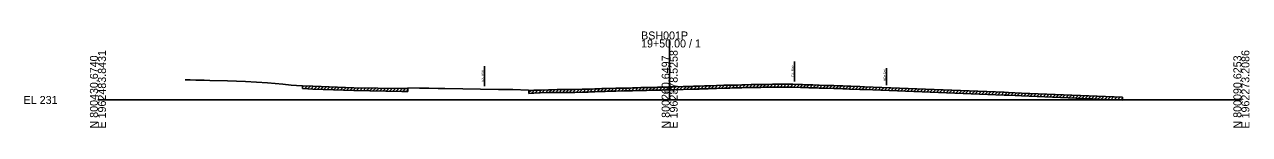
# Model space of a CAD drawing. Extents: x -26 to 1403, y -10 to 19587.
# Drawn here: x -25.7 to 402.8, y 3490.3 to 3524 of the extents above; entities that cross this region are included whole.
import ezdxf

# ---------------------------------------------------------------- set-up
doc = ezdxf.new("R2010")
doc.units = 0
for name, color, linetype in [('Default', 7, 'Continuous'), ('RD_GPK_XS_Cell', 7, 'Continuous'), ('RD_XS_ExGround', 7, 'Continuous'), ('RD_XS_ExPaveRet', 7, 'Continuous'), ('RD_XS_ExRW', 7, 'Continuous'), ('RD_XS_NewRW', 7, 'Continuous'), ('RD_XS_TX_Elev_EX', 7, 'Continuous')]:
    doc.layers.add(name, color=color, linetype=linetype)

msp = doc.modelspace()

# ---------------------------------------------------------------- linework, layer by layer
at = {"layer": 'RD_GPK_XS_Cell'}
for p, q in [((200, 3500), (200, 3521.2)), ((0, 3500), (200, 3500)), ((200, 3500), (400, 3500))]:
    msp.add_line(p, q, dxfattribs=at)
at = {"layer": 'RD_XS_ExGround'}
msp.add_lwpolyline([(30.51, 3507.07), (31.26, 3507.05), (32.27, 3507.02), (34.23, 3506.99), (34.54, 3506.98), (35.46, 3506.97), (37.12, 3506.93), (39.18, 3506.87), (45.29, 3506.73), (51.6, 3506.44), (59.31, 3505.96), (64.64, 3505.48), (67.56, 3505.22), (69.44, 3505.1), (71.57, 3504.97), (75.23, 3504.8), (89.48, 3504.28), (106.25, 3504.01), (108.35, 3503.97), (108.45, 3504.22), (112.53, 3504.15), (115.74, 3504.1), (118.96, 3504.04), (121.32, 3504.02), (140.09, 3503.71), (143.93, 3503.66), (145.18, 3503.61), (150.67, 3503.43), (150.77, 3503.18), (150.79, 3503.32), (151.75, 3503.36), (152.52, 3503.38), (154.65, 3503.45), (157.62, 3503.56), (158.14, 3503.57), (160.67, 3503.62), (161.67, 3503.62), (162.1, 3503.62), (163.47, 3503.62), (165.46, 3503.64), (166.37, 3503.65), (166.78, 3503.66), (169.36, 3503.73), (170.2, 3503.75), (171.49, 3503.79), (172.3, 3503.82), (173.84, 3503.88), (175.23, 3503.93), (175.62, 3503.94), (176.27, 3503.97), (177.47, 3504.02), (178.18, 3504.04), (181.18, 3504.09), (184.02, 3504.15), (184.7, 3504.17), (185.73, 3504.19), (186.95, 3504.22), (188.32, 3504.26), (189.91, 3504.32), (190.5, 3504.33), (191.94, 3504.37), (192.85, 3504.38), (195.24, 3504.42), (195.79, 3504.44), (197.4, 3504.47), (198.73, 3504.51), (199.2, 3504.52), (200, 3504.55), (201.04, 3504.58), (201.69, 3504.6), (204.75, 3504.69), (207.58, 3504.77), (208.32, 3504.79), (209.52, 3504.82), (210.15, 3504.84), (210.53, 3504.86), (212.16, 3504.91), (213.47, 3504.95), (214.26, 3504.98), (216.4, 3505.06), (219, 3505.13), (219.32, 3505.13), (221.02, 3505.17), (222.25, 3505.2), (223.73, 3505.24), (225.2, 3505.28), (226.45, 3505.33), (228.54, 3505.4), (229.84, 3505.39), (231.08, 3505.4), (231.89, 3505.42), (233.21, 3505.45), (233.71, 3505.46), (234.01, 3505.47), (236, 3505.51), (236.36, 3505.52), (236.91, 3505.52), (238.03, 3505.51), (239.19, 3505.51), (239.91, 3505.5), (243.03, 3505.48), (245.76, 3505.39), (246.43, 3505.38), (247.46, 3505.35), (248.23, 3505.32), (248.73, 3505.31), (250.09, 3505.26), (251.67, 3505.21), (252.29, 3505.19), (254.56, 3505.12), (257.45, 3505.04), (259.15, 3504.98), (260.54, 3504.93), (261.99, 3504.87), (262.86, 3504.84), (263.37, 3504.82), (266.52, 3504.71), (268.11, 3504.66), (316.99, 3502.69), (318.58, 3502.63), (323.1, 3502.44), (358.39, 3500.93)], dxfattribs=at)
at = {"layer": 'RD_XS_ExPaveRet'}
for p, q in [((227.88, 3504.38), (228.9, 3505.4)), ((230.25, 3504.39), (231.26, 3505.41)), ((231.45, 3504.41), (232.47, 3505.43)), ((232.65, 3504.44), (233.67, 3505.46)), ((233.85, 3504.46), (234.88, 3505.49)), ((235.06, 3504.49), (236.08, 3505.51)), ((236.27, 3504.52), (237.27, 3505.52)), ((237.44, 3504.52), (238.44, 3505.51)), ((238.62, 3504.51), (239.61, 3505.51)), ((239.79, 3504.5), (240.78, 3505.49)), ((240.95, 3504.49), (241.95, 3505.48)), ((242.12, 3504.48), (243.11, 3505.47)), ((243.28, 3504.47), (244.26, 3505.44)), ((244.43, 3504.43), (245.4, 3505.4)), ((71.57, 3503.97), (71.57, 3504.97)), ((71.57, 3504.45), (72.06, 3504.95)), ((72.23, 3503.94), (73.19, 3504.89)), ((73.36, 3503.89), (74.31, 3504.84)), ((74.49, 3503.84), (75.44, 3504.79)), ((75.62, 3503.79), (76.58, 3504.75)), ((76.75, 3503.75), (77.72, 3504.71)), ((77.89, 3503.7), (78.85, 3504.67)), ((79.02, 3503.66), (79.99, 3504.63)), ((80.16, 3503.62), (81.13, 3504.59)), ((81.3, 3503.58), (82.26, 3504.54)), ((82.43, 3503.54), (83.4, 3504.5)), ((83.57, 3503.5), (84.54, 3504.46)), ((84.71, 3503.46), (85.67, 3504.42)), ((85.84, 3503.41), (86.81, 3504.38)), ((86.98, 3503.37), (87.94, 3504.34)), ((88.12, 3503.33), (89.08, 3504.3)), ((89.25, 3503.29), (90.23, 3504.27)), ((90.41, 3503.27), (91.39, 3504.25)), ((91.57, 3503.25), (92.55, 3504.23)), ((92.73, 3503.23), (93.71, 3504.21)), ((93.88, 3503.21), (94.87, 3504.19)), ((95.04, 3503.19), (96.03, 3504.17)), ((96.2, 3503.17), (97.19, 3504.15)), ((97.36, 3503.15), (98.35, 3504.14)), ((98.52, 3503.13), (99.5, 3504.12)), ((99.68, 3503.11), (100.66, 3504.1)), ((100.84, 3503.09), (101.82, 3504.08)), ((102, 3503.08), (102.98, 3504.06)), ((103.16, 3503.06), (104.14, 3504.04)), ((104.32, 3503.04), (105.3, 3504.02)), ((105.47, 3503.02), (106.46, 3504)), ((106.63, 3503), (107.62, 3503.98)), ((107.79, 3502.98), (108.35, 3503.53)), ((108.35, 3502.97), (108.35, 3503.97)), ((150.79, 3502.68), (151.45, 3503.34)), ((150.79, 3502.32), (150.79, 3503.32)), ((151.64, 3502.35), (152.67, 3503.39)), ((152.86, 3502.39), (153.89, 3503.43)), ((154.08, 3502.43), (155.11, 3503.47)), ((155.3, 3502.48), (156.33, 3503.51)), ((156.52, 3502.52), (157.56, 3503.56)), ((157.74, 3502.56), (158.76, 3503.58)), ((158.94, 3502.59), (159.96, 3503.61)), ((160.14, 3502.61), (161.15, 3503.62)), ((161.33, 3502.62), (162.33, 3503.62)), ((162.51, 3502.62), (163.51, 3503.62)), ((163.69, 3502.62), (164.7, 3503.63)), ((164.88, 3502.63), (165.89, 3503.65)), ((166.07, 3502.65), (167.09, 3503.67)), ((167.27, 3502.67), (168.3, 3503.7)), ((168.48, 3502.7), (169.51, 3503.73)), ((169.69, 3502.74), (170.72, 3503.77)), ((170.91, 3502.77), (171.94, 3503.81)), ((172.12, 3502.81), (173.16, 3503.85)), ((173.35, 3502.86), (174.39, 3503.9)), ((174.57, 3502.9), (175.61, 3503.94)), ((175.8, 3502.95), (176.84, 3503.99)), ((177.02, 3503), (178.06, 3504.04)), ((178.24, 3503.04), (179.26, 3504.06)), ((179.44, 3503.06), (180.46, 3504.08)), ((180.64, 3503.08), (181.66, 3504.1)), ((181.84, 3503.11), (182.87, 3504.13)), ((183.05, 3503.13), (184.07, 3504.15)), ((184.25, 3503.16), (185.27, 3504.18)), ((185.46, 3503.19), (186.48, 3504.21)), ((186.67, 3503.22), (187.69, 3504.25)), ((187.88, 3503.25), (188.91, 3504.28)), ((189.09, 3503.29), (190.13, 3504.32)), ((190.31, 3503.33), (191.34, 3504.35)), ((191.52, 3503.36), (192.53, 3504.37)), ((192.71, 3503.38), (193.73, 3504.39)), ((193.91, 3503.4), (194.93, 3504.42)), ((195.12, 3503.42), (196.14, 3504.44)), ((196.32, 3503.45), (197.34, 3504.47)), ((197.52, 3503.47), (198.55, 3504.5)), ((198.73, 3503.51), (199.77, 3504.54)), ((199.95, 3503.55), (200.99, 3504.58)), ((201.17, 3503.59), (202.2, 3504.62)), ((202.38, 3503.62), (203.42, 3504.65)), ((203.6, 3503.66), (204.63, 3504.69)), ((204.81, 3503.69), (205.84, 3504.72)), ((206.02, 3503.73), (207.05, 3504.75)), ((207.23, 3503.76), (208.26, 3504.79)), ((208.45, 3503.79), (209.48, 3504.82)), ((209.66, 3503.83), (210.69, 3504.86)), ((210.88, 3503.87), (211.91, 3504.9)), ((212.09, 3503.91), (213.13, 3504.94)), ((213.31, 3503.95), (214.35, 3504.98)), ((214.53, 3503.99), (215.57, 3505.03)), ((215.76, 3504.03), (216.79, 3505.07)), ((216.97, 3504.07), (218, 3505.1)), ((218.18, 3504.1), (219.21, 3505.13)), ((219.39, 3504.13), (220.41, 3505.15)), ((220.59, 3504.16), (221.61, 3505.18)), ((221.8, 3504.18), (222.82, 3505.21)), ((223.01, 3504.22), (224.04, 3505.25)), ((224.22, 3504.25), (225.25, 3505.29)), ((225.44, 3504.29), (226.47, 3505.33)), ((226.66, 3504.33), (227.7, 3505.37)), ((229.08, 3504.4), (230.07, 3505.39)), ((245.57, 3504.4), (246.55, 3505.37)), ((246.72, 3504.37), (247.69, 3505.34)), ((247.86, 3504.34), (248.83, 3505.3)), ((249, 3504.3), (249.97, 3505.27)), ((250.14, 3504.26), (251.11, 3505.23)), ((251.28, 3504.22), (252.25, 3505.19)), ((252.42, 3504.18), (253.4, 3505.16)), ((253.57, 3504.15), (254.54, 3505.12)), ((254.71, 3504.12), (255.68, 3505.09)), ((255.86, 3504.08), (256.83, 3505.06)), ((257, 3504.05), (257.97, 3505.02)), ((258.15, 3504.02), (259.12, 3504.99)), ((259.29, 3503.98), (260.25, 3504.94)), ((260.42, 3503.93), (261.38, 3504.9)), ((261.55, 3503.89), (262.52, 3504.86)), ((262.69, 3503.85), (263.65, 3504.81)), ((263.83, 3503.81), (264.79, 3504.77)), ((264.96, 3503.76), (265.93, 3504.73)), ((266.1, 3503.72), (267.07, 3504.69)), ((267.24, 3503.68), (268.21, 3504.65)), ((268.38, 3503.65), (269.34, 3504.61)), ((269.51, 3503.6), (270.47, 3504.56)), ((270.64, 3503.56), (271.61, 3504.52)), ((271.78, 3503.51), (272.74, 3504.47)), ((272.91, 3503.46), (273.87, 3504.43)), ((274.04, 3503.42), (275, 3504.38)), ((275.18, 3503.37), (276.14, 3504.34)), ((276.31, 3503.33), (277.27, 3504.29)), ((277.44, 3503.28), (278.4, 3504.24)), ((278.57, 3503.24), (279.53, 3504.2)), ((279.71, 3503.19), (280.67, 3504.15)), ((280.84, 3503.15), (281.8, 3504.11)), ((281.97, 3503.1), (282.93, 3504.06)), ((283.1, 3503.06), (284.06, 3504.02)), ((284.24, 3503.01), (285.2, 3503.97)), ((285.37, 3502.96), (286.33, 3503.93)), ((286.5, 3502.92), (287.46, 3503.88)), ((287.63, 3502.87), (288.59, 3503.83)), ((288.77, 3502.83), (289.73, 3503.79)), ((289.9, 3502.78), (290.86, 3503.74)), ((291.03, 3502.74), (291.99, 3503.7)), ((292.16, 3502.69), (293.12, 3503.65)), ((293.3, 3502.65), (294.26, 3503.61)), ((294.43, 3502.6), (295.39, 3503.56)), ((295.56, 3502.55), (296.52, 3503.52)), ((296.69, 3502.51), (297.65, 3503.47)), ((297.83, 3502.46), (298.79, 3503.43)), ((298.96, 3502.42), (299.92, 3503.38)), ((300.09, 3502.37), (301.05, 3503.33)), ((301.22, 3502.33), (302.19, 3503.29)), ((302.36, 3502.28), (303.32, 3503.24)), ((303.49, 3502.24), (304.45, 3503.2)), ((304.62, 3502.19), (305.58, 3503.15)), ((305.75, 3502.15), (306.72, 3503.11)), ((306.89, 3502.1), (307.85, 3503.06)), ((308.02, 3502.05), (308.98, 3503.02)), ((309.15, 3502.01), (310.11, 3502.97)), ((310.28, 3501.96), (311.25, 3502.92)), ((311.42, 3501.92), (312.38, 3502.88)), ((312.55, 3501.87), (313.51, 3502.83)), ((313.68, 3501.83), (314.64, 3502.79)), ((314.81, 3501.78), (315.78, 3502.74)), ((315.95, 3501.74), (316.91, 3502.7)), ((317.08, 3501.69), (318.04, 3502.65)), ((318.21, 3501.64), (319.17, 3502.6)), ((319.34, 3501.6), (320.3, 3502.56)), ((320.47, 3501.55), (321.44, 3502.51)), ((321.61, 3501.51), (322.57, 3502.47)), ((322.74, 3501.46), (323.7, 3502.42)), ((323.87, 3501.41), (324.83, 3502.37)), ((325, 3501.36), (325.96, 3502.32)), ((326.13, 3501.31), (327.09, 3502.27)), ((327.26, 3501.27), (328.22, 3502.22)), ((328.39, 3501.22), (329.34, 3502.18)), ((329.52, 3501.17), (330.47, 3502.13)), ((330.64, 3501.12), (331.6, 3502.08)), ((331.77, 3501.07), (332.73, 3502.03)), ((332.9, 3501.02), (333.86, 3501.98)), ((334.03, 3500.97), (334.99, 3501.93)), ((335.16, 3500.93), (336.12, 3501.88)), ((336.29, 3500.88), (337.25, 3501.84)), ((337.42, 3500.83), (338.38, 3501.79)), ((338.55, 3500.78), (339.51, 3501.74)), ((339.68, 3500.73), (340.64, 3501.69)), ((340.81, 3500.68), (341.77, 3501.64)), ((341.94, 3500.63), (342.9, 3501.59)), ((343.07, 3500.58), (344.03, 3501.54)), ((344.2, 3500.54), (345.16, 3501.49)), ((345.33, 3500.49), (346.29, 3501.45)), ((346.46, 3500.44), (347.42, 3501.4)), ((347.59, 3500.39), (348.54, 3501.35)), ((348.72, 3500.34), (349.67, 3501.3)), ((349.84, 3500.29), (350.8, 3501.25)), ((350.97, 3500.24), (351.93, 3501.2)), ((352.1, 3500.2), (353.06, 3501.15)), ((353.23, 3500.15), (354.19, 3501.11)), ((354.36, 3500.1), (355.32, 3501.06)), ((355.49, 3500.05), (356.45, 3501.01)), ((356.62, 3500), (357.58, 3500.96)), ((357.75, 3499.95), (358.39, 3500.59)), ((358.39, 3499.93), (358.39, 3500.93))]:
    msp.add_line(p, q, dxfattribs=at)
for points in [[(71.57, 3503.97), (75.23, 3503.8), (89.48, 3503.28), (106.25, 3503.01), (108.35, 3502.97)], [(150.79, 3502.32), (150.79, 3502.32), (151.75, 3502.36), (152.52, 3502.38), (154.65, 3502.45), (157.62, 3502.56), (158.14, 3502.57), (160.67, 3502.62), (161.67, 3502.62), (162.1, 3502.62), (163.47, 3502.62), (165.46, 3502.64), (166.37, 3502.65), (166.78, 3502.66), (169.36, 3502.73), (170.2, 3502.75), (171.49, 3502.79), (172.3, 3502.82), (173.84, 3502.88), (175.23, 3502.93), (175.62, 3502.94), (176.27, 3502.97), (177.47, 3503.02), (178.18, 3503.04), (181.18, 3503.09), (184.02, 3503.15), (184.7, 3503.17), (185.73, 3503.19), (186.95, 3503.22), (188.32, 3503.26), (189.91, 3503.32), (190.5, 3503.33), (191.94, 3503.37), (192.85, 3503.38), (195.24, 3503.42), (195.79, 3503.44), (197.4, 3503.47), (198.73, 3503.51), (199.2, 3503.52), (200, 3503.55), (201.04, 3503.58), (201.69, 3503.6), (204.75, 3503.69), (207.58, 3503.77), (208.32, 3503.79), (209.52, 3503.82), (210.15, 3503.84), (210.53, 3503.86), (212.16, 3503.91), (213.47, 3503.95), (214.26, 3503.98), (216.4, 3504.06), (219, 3504.13), (219.32, 3504.13), (221.02, 3504.17), (222.25, 3504.2), (223.73, 3504.24), (225.2, 3504.28), (226.45, 3504.33), (228.54, 3504.4), (229.84, 3504.39), (231.08, 3504.4), (231.89, 3504.42), (233.21, 3504.45), (233.71, 3504.46), (234.01, 3504.47), (236, 3504.51), (236.36, 3504.52), (236.91, 3504.52), (238.03, 3504.51), (239.19, 3504.51), (239.91, 3504.5), (243.03, 3504.48), (245.76, 3504.39), (246.43, 3504.38), (247.46, 3504.35), (248.23, 3504.32), (248.73, 3504.31), (250.09, 3504.26), (251.67, 3504.21), (252.29, 3504.19), (254.56, 3504.12), (257.45, 3504.04), (259.15, 3503.98), (260.54, 3503.93), (261.99, 3503.87), (262.86, 3503.84), (263.37, 3503.82), (266.52, 3503.71), (268.11, 3503.66), (316.99, 3501.69), (318.58, 3501.63), (323.1, 3501.44), (358.39, 3499.93)]]:
    msp.add_lwpolyline(points, dxfattribs=at)
at = {"layer": 'RD_XS_ExRW'}
for p, q in [((135.18, 3504.79), (135.18, 3511.79)), ((243.66, 3506.46), (243.66, 3513.46))]:
    msp.add_line(p, q, dxfattribs=at)
at = {"layer": 'RD_XS_NewRW'}
msp.add_line((275.8, 3511.16), (275.8, 3505.16), dxfattribs=at)

# ---------------------------------------------------------------- texts
at = {"layer": 'Default'}
msp.add_text('-', height=0.0001, dxfattribs=at).set_placement((0, 3500))
at = {"layer": 'RD_GPK_XS_Cell'}
for s, p in [('BSH001P', (190, 3521.2)), ('19+50.00 / 1', (190, 3518.4)), ('EL 231', (-26, 3498.6))]:
    msp.add_text(s, height=2.8, dxfattribs=at).set_placement(p)
for s, p in [('N 800430.6740', (0, 3490)), ('E 1962483.8431', (2.8, 3490)), ('N 800260.6497', (200, 3490)), ('E 1962378.5258', (202.8, 3490)), ('N 800090.6253', (400, 3490)), ('E 1962273.2086', (402.8, 3490))]:
    msp.add_text(s, height=2.8, rotation=90, dxfattribs=at).set_placement(p)
at = {"layer": 'RD_XS_ExRW'}
for p in [(134.93, 3506.46), (243.41, 3508.13)]:
    msp.add_text('EX. R/W ', height=0.75, rotation=90, dxfattribs=at).set_placement(p)
at = {"layer": 'RD_XS_NewRW'}
msp.add_text('NEW R/W ', height=0.65, rotation=90, dxfattribs=at).set_placement((275.53, 3506.72))
at = {"layer": 'RD_XS_TX_Elev_EX'}
msp.add_text('235.55', height=1, dxfattribs=at).set_placement((197.95, 3502.05))

doc.saveas('drawing.dxf')
